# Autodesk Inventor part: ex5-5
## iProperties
Shininess: 64.0
Length Units: 11272
Angle Units: 11279
Time Units: 11290
Mass Units: 11286
Length Display Precision: 3
Angle Display Precision: 2
Compacted: True
Part Number: ex5-5
Document SubType Name: Modeling
Created: 2002-09
Designer: Elise Moss
Density: 0.0
Volumn: 0.0
Area: 0.0
PropertySet Name: Model Information
Control State: 0
Master: False
Checked Out: False
Author: Elise Moss
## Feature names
1. Revolution1
2. Hole1
3. Shell1
